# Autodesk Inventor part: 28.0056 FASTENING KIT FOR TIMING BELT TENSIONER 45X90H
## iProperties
Created: 2007-06
Part Number: 28.0056 FASTENING KIT FOR TIMING BELT TENSIONER 45X90H
Document SubType Name: Modeling
Designer: Andy Moles
Material: Aluminum-6061
Density: 2.71 g/cm^3
Author: Andy Moles
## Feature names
1. Extrusion1
2. Hole2
